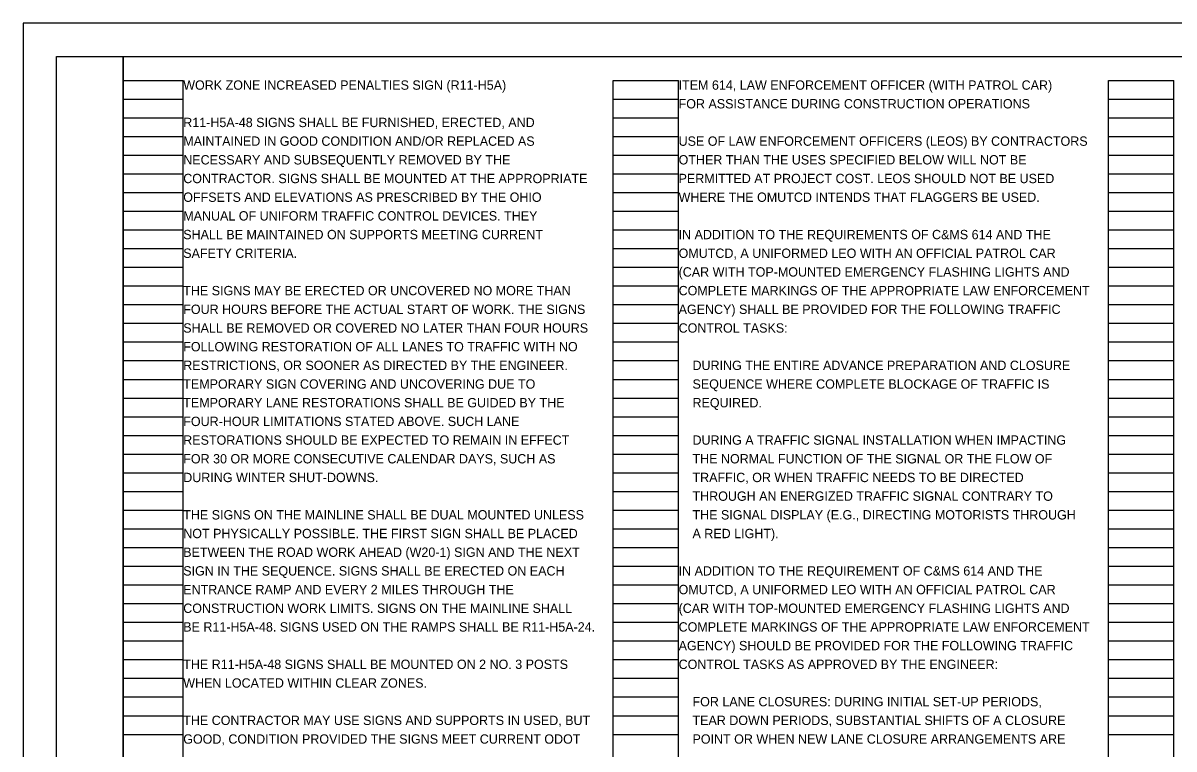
# Model space of a CAD drawing. Extents: x 0 to 34, y 0 to 22.
# Drawn here: x 0 to 17.24, y 11.12 to 22 of the extents above; entities that cross this region are included whole.
import ezdxf

# ---------------------------------------------------------------- set-up
doc = ezdxf.new("R2010")
doc.units = 0
for name, color, linetype in [('SH_Border', 7, 'Continuous'), ('SH_Cut_Line', 7, 'Continuous'), ('SH_Data', 7, 'Continuous'), ('SH_Text', 7, 'Continuous')]:
    doc.layers.add(name, color=color, linetype=linetype)

msp = doc.modelspace()

# ---------------------------------------------------------------- linework, layer by layer
at = {"layer": 'SH_Border'}
for points in [[(0.5, 21.5), (1.5, 21.5), (1.5, 0.5), (0.5, 0.5)], [(1.5, 21.5), (33.5, 21.5), (33.5, 0.5), (1.5, 0.5)]]:
    msp.add_lwpolyline(points, close=True, dxfattribs=at)
at = {"layer": 'SH_Cut_Line'}
msp.add_lwpolyline([(0, 0), (34, 0), (34, 22), (0, 22)], close=True, dxfattribs=at)
at = {"layer": 'SH_Data'}
for p, q in [((1.5, 0.98), (1.5, 21.14)), ((1.5, 21.14), (2.4, 21.14)), ((2.4, 0.98), (2.4, 21.14)), ((8.84, 0.98), (8.84, 21.14)), ((8.84, 21.14), (9.82, 21.14)), ((9.82, 0.98), (9.82, 21.14)), ((16.26, 0.98), (16.26, 21.14)), ((16.26, 21.14), (17.24, 21.14)), ((17.24, 0.98), (17.24, 21.14)), ((1.5, 20.86), (2.4, 20.86)), ((8.84, 20.86), (9.82, 20.86)), ((16.26, 20.86), (17.24, 20.86)), ((1.5, 20.58), (2.4, 20.58)), ((8.84, 20.58), (9.82, 20.58)), ((16.26, 20.58), (17.24, 20.58)), ((1.5, 20.3), (2.4, 20.3)), ((8.84, 20.3), (9.82, 20.3)), ((16.26, 20.3), (17.24, 20.3)), ((1.5, 20.02), (2.4, 20.02)), ((8.84, 20.02), (9.82, 20.02)), ((16.26, 20.02), (17.24, 20.02)), ((1.5, 19.74), (2.4, 19.74)), ((8.84, 19.74), (9.82, 19.74)), ((16.26, 19.74), (17.24, 19.74)), ((1.5, 19.46), (2.4, 19.46)), ((8.84, 19.46), (9.82, 19.46)), ((16.26, 19.46), (17.24, 19.46)), ((1.5, 19.18), (2.4, 19.18)), ((8.84, 19.18), (9.82, 19.18)), ((16.26, 19.18), (17.24, 19.18)), ((1.5, 18.9), (2.4, 18.9)), ((8.84, 18.9), (9.82, 18.9)), ((16.26, 18.9), (17.24, 18.9)), ((1.5, 18.62), (2.4, 18.62)), ((8.84, 18.62), (9.82, 18.62)), ((16.26, 18.62), (17.24, 18.62)), ((1.5, 18.34), (2.4, 18.34)), ((8.84, 18.34), (9.82, 18.34)), ((16.26, 18.34), (17.24, 18.34)), ((1.5, 18.06), (2.4, 18.06)), ((8.84, 18.06), (9.82, 18.06)), ((16.26, 18.06), (17.24, 18.06)), ((1.5, 17.78), (2.4, 17.78)), ((8.84, 17.78), (9.82, 17.78)), ((16.26, 17.78), (17.24, 17.78)), ((1.5, 17.5), (2.4, 17.5)), ((8.84, 17.5), (9.82, 17.5)), ((16.26, 17.5), (17.24, 17.5)), ((1.5, 17.22), (2.4, 17.22)), ((8.84, 17.22), (9.82, 17.22)), ((16.26, 17.22), (17.24, 17.22)), ((1.5, 16.94), (2.4, 16.94)), ((8.84, 16.94), (9.82, 16.94)), ((16.26, 16.94), (17.24, 16.94)), ((1.5, 16.66), (2.4, 16.66)), ((8.84, 16.66), (9.82, 16.66)), ((16.26, 16.66), (17.24, 16.66)), ((1.5, 16.38), (2.4, 16.38)), ((8.84, 16.38), (9.82, 16.38)), ((16.26, 16.38), (17.24, 16.38)), ((1.5, 16.1), (2.4, 16.1)), ((8.84, 16.1), (9.82, 16.1)), ((16.26, 16.1), (17.24, 16.1)), ((1.5, 15.82), (2.4, 15.82)), ((8.84, 15.82), (9.82, 15.82)), ((16.26, 15.82), (17.24, 15.82)), ((1.5, 15.54), (2.4, 15.54)), ((8.84, 15.54), (9.82, 15.54)), ((16.26, 15.54), (17.24, 15.54)), ((1.5, 15.26), (2.4, 15.26)), ((8.84, 15.26), (9.82, 15.26)), ((16.26, 15.26), (17.24, 15.26)), ((1.5, 14.98), (2.4, 14.98)), ((8.84, 14.98), (9.82, 14.98)), ((16.26, 14.98), (17.24, 14.98)), ((1.5, 14.7), (2.4, 14.7)), ((8.84, 14.7), (9.82, 14.7)), ((16.26, 14.7), (17.24, 14.7)), ((1.5, 14.42), (2.4, 14.42)), ((8.84, 14.42), (9.82, 14.42)), ((16.26, 14.42), (17.24, 14.42)), ((1.5, 14.14), (2.4, 14.14)), ((8.84, 14.14), (9.82, 14.14)), ((16.26, 14.14), (17.24, 14.14)), ((1.5, 13.86), (2.4, 13.86)), ((8.84, 13.86), (9.82, 13.86)), ((16.26, 13.86), (17.24, 13.86)), ((1.5, 13.58), (2.4, 13.58)), ((8.84, 13.58), (9.82, 13.58)), ((16.26, 13.58), (17.24, 13.58)), ((1.5, 13.3), (2.4, 13.3)), ((8.84, 13.3), (9.82, 13.3)), ((16.26, 13.3), (17.24, 13.3)), ((1.5, 13.02), (2.4, 13.02)), ((8.84, 13.02), (9.82, 13.02)), ((16.26, 13.02), (17.24, 13.02)), ((1.5, 12.74), (2.4, 12.74)), ((8.84, 12.74), (9.82, 12.74)), ((16.26, 12.74), (17.24, 12.74)), ((1.5, 12.46), (2.4, 12.46)), ((8.84, 12.46), (9.82, 12.46)), ((16.26, 12.46), (17.24, 12.46)), ((1.5, 12.18), (2.4, 12.18)), ((8.84, 12.18), (9.82, 12.18)), ((16.26, 12.18), (17.24, 12.18)), ((1.5, 11.9), (2.4, 11.9)), ((8.84, 11.9), (9.82, 11.9)), ((16.26, 11.9), (17.24, 11.9)), ((1.5, 11.62), (2.4, 11.62)), ((8.84, 11.62), (9.82, 11.62)), ((16.26, 11.62), (17.24, 11.62)), ((1.5, 11.34), (2.4, 11.34)), ((8.84, 11.34), (9.82, 11.34)), ((16.26, 11.34), (17.24, 11.34))]:
    msp.add_line(p, q, dxfattribs=at)

# ---------------------------------------------------------------- texts
at = {"layer": 'SH_Text'}
for s, p in [('WORK ZONE INCREASED PENALTIES SIGN (R11-H5A)', (2.4, 21)), ('ITEM 614, LAW ENFORCEMENT OFFICER (WITH PATROL CAR)', (9.82, 21)), ('FOR ASSISTANCE DURING CONSTRUCTION OPERATIONS', (9.82, 20.72)), ('R11-H5A-48 SIGNS SHALL BE FURNISHED, ERECTED, AND', (2.4, 20.44)), ('MAINTAINED IN GOOD CONDITION AND/OR REPLACED AS', (2.4, 20.16)), ('USE OF LAW ENFORCEMENT OFFICERS (LEOS) BY CONTRACTORS', (9.82, 20.16)), ('NECESSARY AND SUBSEQUENTLY REMOVED BY THE', (2.4, 19.88)), ('OTHER THAN THE USES SPECIFIED BELOW WILL NOT BE', (9.82, 19.88)), ('CONTRACTOR. SIGNS SHALL BE MOUNTED AT THE APPROPRIATE', (2.4, 19.6)), ('PERMITTED AT PROJECT COST. LEOS SHOULD NOT BE USED', (9.82, 19.6)), ('OFFSETS AND ELEVATIONS AS PRESCRIBED BY THE OHIO', (2.4, 19.32)), ('WHERE THE OMUTCD INTENDS THAT FLAGGERS BE USED.', (9.82, 19.32)), ('MANUAL OF UNIFORM TRAFFIC CONTROL DEVICES. THEY', (2.4, 19.04)), ('SHALL BE MAINTAINED ON SUPPORTS MEETING CURRENT', (2.4, 18.76)), ('IN ADDITION TO THE REQUIREMENTS OF C&MS 614 AND THE', (9.82, 18.76)), ('SAFETY CRITERIA.', (2.4, 18.48)), ('OMUTCD, A UNIFORMED LEO WITH AN OFFICIAL PATROL CAR', (9.82, 18.48)), ('(CAR WITH TOP-MOUNTED EMERGENCY FLASHING LIGHTS AND', (9.82, 18.2)), ('THE SIGNS MAY BE ERECTED OR UNCOVERED NO MORE THAN', (2.4, 17.92)), ('COMPLETE MARKINGS OF THE APPROPRIATE LAW ENFORCEMENT', (9.82, 17.92)), ('FOUR HOURS BEFORE THE ACTUAL START OF WORK. THE SIGNS', (2.4, 17.64)), ('AGENCY) SHALL BE PROVIDED FOR THE FOLLOWING TRAFFIC', (9.82, 17.64)), ('SHALL BE REMOVED OR COVERED NO LATER THAN FOUR HOURS', (2.4, 17.36)), ('CONTROL TASKS:', (9.82, 17.36)), ('FOLLOWING RESTORATION OF ALL LANES TO TRAFFIC WITH NO', (2.4, 17.08)), ('RESTRICTIONS, OR SOONER AS DIRECTED BY THE ENGINEER.', (2.4, 16.8)), ('    DURING THE ENTIRE ADVANCE PREPARATION AND CLOSURE', (9.82, 16.8)), ('TEMPORARY SIGN COVERING AND UNCOVERING DUE TO', (2.4, 16.52)), ('    SEQUENCE WHERE COMPLETE BLOCKAGE OF TRAFFIC IS', (9.82, 16.52)), ('TEMPORARY LANE RESTORATIONS SHALL BE GUIDED BY THE', (2.4, 16.24)), ('    REQUIRED.', (9.82, 16.24)), ('FOUR-HOUR LIMITATIONS STATED ABOVE. SUCH LANE', (2.4, 15.96)), ('RESTORATIONS SHOULD BE EXPECTED TO REMAIN IN EFFECT', (2.4, 15.68)), ('    DURING A TRAFFIC SIGNAL INSTALLATION WHEN IMPACTING', (9.82, 15.68)), ('FOR 30 OR MORE CONSECUTIVE CALENDAR DAYS, SUCH AS', (2.4, 15.4)), ('    THE NORMAL FUNCTION OF THE SIGNAL OR THE FLOW OF', (9.82, 15.4)), ('DURING WINTER SHUT-DOWNS.', (2.4, 15.12)), ('    TRAFFIC, OR WHEN TRAFFIC NEEDS TO BE DIRECTED', (9.82, 15.12)), ('    THROUGH AN ENERGIZED TRAFFIC SIGNAL CONTRARY TO', (9.82, 14.84)), ('THE SIGNS ON THE MAINLINE SHALL BE DUAL MOUNTED UNLESS', (2.4, 14.56)), ('    THE SIGNAL DISPLAY (E.G., DIRECTING MOTORISTS THROUGH', (9.82, 14.56)), ('NOT PHYSICALLY POSSIBLE. THE FIRST SIGN SHALL BE PLACED', (2.4, 14.28)), ('    A RED LIGHT).', (9.82, 14.28)), ('BETWEEN THE ROAD WORK AHEAD (W20-1) SIGN AND THE NEXT', (2.4, 14)), ('SIGN IN THE SEQUENCE. SIGNS SHALL BE ERECTED ON EACH', (2.4, 13.72)), ('IN ADDITION TO THE REQUIREMENT OF C&MS 614 AND THE', (9.82, 13.72)), ('ENTRANCE RAMP AND EVERY 2 MILES THROUGH THE', (2.4, 13.44)), ('OMUTCD, A UNIFORMED LEO WITH AN OFFICIAL PATROL CAR', (9.82, 13.44)), ('CONSTRUCTION WORK LIMITS. SIGNS ON THE MAINLINE SHALL', (2.4, 13.16)), ('(CAR WITH TOP-MOUNTED EMERGENCY FLASHING LIGHTS AND', (9.82, 13.16)), ('BE R11-H5A-48. SIGNS USED ON THE RAMPS SHALL BE R11-H5A-24.', (2.4, 12.88)), ('COMPLETE MARKINGS OF THE APPROPRIATE LAW ENFORCEMENT', (9.82, 12.88)), ('AGENCY) SHOULD BE PROVIDED FOR THE FOLLOWING TRAFFIC', (9.82, 12.6)), ('THE R11-H5A-48 SIGNS SHALL BE MOUNTED ON 2 NO. 3 POSTS', (2.4, 12.32)), ('CONTROL TASKS AS APPROVED BY THE ENGINEER:', (9.82, 12.32)), ('WHEN LOCATED WITHIN CLEAR ZONES.', (2.4, 12.04)), ('    FOR LANE CLOSURES: DURING INITIAL SET-UP PERIODS,', (9.82, 11.76)), ('THE CONTRACTOR MAY USE SIGNS AND SUPPORTS IN USED, BUT', (2.4, 11.48)), ('    TEAR DOWN PERIODS, SUBSTANTIAL SHIFTS OF A CLOSURE', (9.82, 11.48)), ('GOOD, CONDITION PROVIDED THE SIGNS MEET CURRENT ODOT', (2.4, 11.2)), ('    POINT OR WHEN NEW LANE CLOSURE ARRANGEMENTS ARE', (9.82, 11.2))]:
    msp.add_text(s, height=0.14, dxfattribs=at).set_placement(p)

doc.saveas('drawing.dxf')
